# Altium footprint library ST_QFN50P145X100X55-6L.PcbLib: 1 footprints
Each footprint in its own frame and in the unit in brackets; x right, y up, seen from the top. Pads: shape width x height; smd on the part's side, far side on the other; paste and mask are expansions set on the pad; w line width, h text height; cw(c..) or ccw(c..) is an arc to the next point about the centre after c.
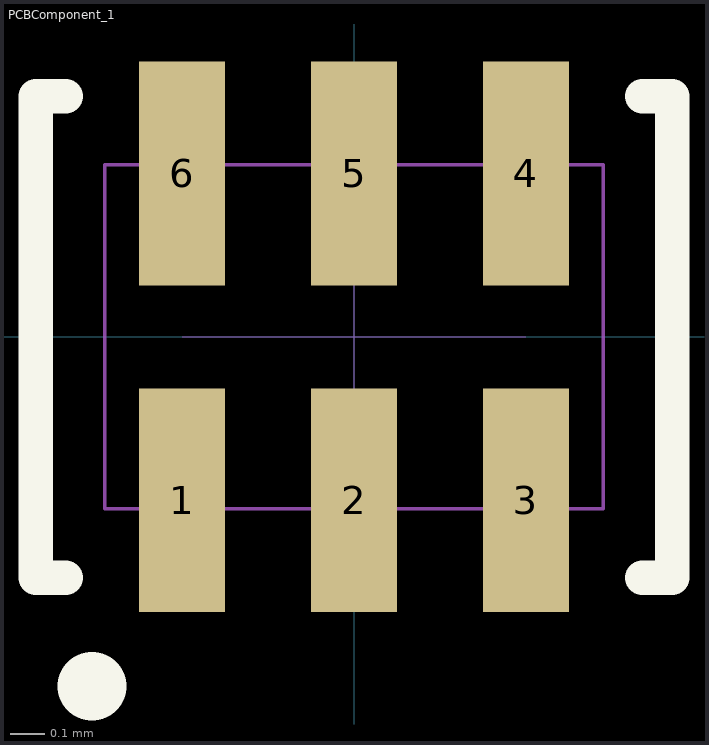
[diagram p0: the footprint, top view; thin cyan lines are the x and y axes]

## PCBComponent_1 [mm]
pads (6):
  rect 0.25x0.65 smd paste-20 mask+0.02: 1(-0.5,-0.475) 2(0,-0.475) 3(0.5,-0.475) 4(0.5,0.475) 5(0,0.475) 6(-0.5,0.475)
Top Overlay:
  circle w0.2: c-0.762,-1.016 r0
  lines w0.1: -0.837,-0.7 -0.925,-0.7 -0.925,0.7 -0.837,0.7 ; 0.838,-0.7 0.925,-0.7 0.925,0.7 0.838,0.7
Top Paste:
  rectangle: -0.618,0.165 -0.382,0.785
  rectangle: -0.118,0.165 0.118,0.785
  rectangle: 0.382,0.165 0.618,0.785
  rectangle: -0.618,-0.785 -0.382,-0.165
  rectangle: -0.118,-0.785 0.118,-0.165
  rectangle: 0.382,-0.785 0.618,-0.165
Mechanical 15:
  lines w0.001: -0.5,0 0.5,0 ; 0,-0.5 0,0.5
  lines w0.01: -0.725,-0.5 -0.725,0.5 0.725,0.5 0.725,-0.5 -0.725,-0.5
3D body: height 0.6, standoff 0, extent -0.725,-0.5 0.725,0.5
3D body: height 1.45, standoff -1.45, extent -0.725,0.5 -0.725,0.5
